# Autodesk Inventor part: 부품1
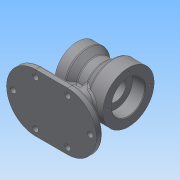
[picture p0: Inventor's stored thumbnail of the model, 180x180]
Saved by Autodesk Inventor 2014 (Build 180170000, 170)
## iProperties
Created: 2020-01
Part Number: 부품1
Material: 일반
Document SubType Name: Modeling
Designer: net
Density: 1 g/cm^3
Appearance: 기본값
Author: net
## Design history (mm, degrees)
sketch "스케치1"
  geometry: L1 (0, 0)-(80, 0); L2 (0, 26)-(20, 26); L3 (20, 26)-(20, 16); L4 (20, 16)-(63, 16); L5 (63, 16)-(63, 20); L6 (63, 20)-(80, 20); L7 (80, 20)-(80, 35); L8 (80, 35)-(64, 35); L9 (64, 35)-(53.289, 27.5); L10 (53.289, 27.5)-(38.897, 27.5); L11 (38.897, 27.5)-(24, 40); L12 (24, 40)-(0, 40); L13 (0, 40)-(0, 26)
  constraints: 26 end point, 8 parallel, 2 perpendicular, 1 horizontal, 1 vertical alignment
  dimensions: "d0" = 80 distance of L1.start L1.end; "d1" = 24 distance of L11.end L12.end; "d2" = 20 distance from line of L3 L2.start; "d3" = 17 distance of L6.end L5.end; "d4" = 80 distance between parallel lines of L7 L13; "d5" = 16 distance of L7.end L8.end; "d6" = 140 deg angle of L10 L11; "d7" = 145 deg angle of L9 L10; "d8" = 80 diameter of L12.end L1; "d9" = 55 diameter of L10 L1; "d10" = 32 diameter of L4 L1; "d11" = 40 diameter of L6 L1; "d12" = 70 diameter of L8 L1; "d13" = 52 diameter of L2 L1
revolve "회전1" sketch "스케치1" stored, may be unused: angle "d14" = 90 deg
fillet "모깎기1" dims "d15" = 0.3
chamfer "모따기1" distance "d16" = 1; stored, may be unused: second distance "d17" = 2, angle "d18" = 45 deg
chamfer "모따기2" distance "d19" = 1; stored, may be unused: second distance "d20" = 2, angle "d21" = 45 deg
node "작업 평면1"
sketch "스케치2"
  geometry: L1 (0, 40)-(24, 40) reference; L2 (0, -40)-(0, 40) reference; L3 (80, -35)-(80, 35) reference; L4 (0, -40)-(24, -40) reference; L5 (64, 35)-(80, 35) reference; L6 (64, -35)-(80, -35) reference; L7 (15, -45)-(65, -45); L8 (65, 45)-(15, 45); L9 (0, 0)-(80, 0); A1 r 45 centre (15, 0) between (15, 45) and (15, -45); A2 r 45 centre (65, 0) between (65, -45) and (65, 45); 4 further points
  constraints: 6 end point, 5 point on circle, 4 midpoint, 4 tangent, 2 centre point, 1 horizontal alignment, 1 parallel, 1 vertical alignment
  dimensions: "d24" = 45 radius of A1; "d25" = 50 distance of L7.end L7.start; "d26" = 70 distance of point (40, 0) point (-30, 0)
extrude "돌출1" join sketch "스케치2" distance "d27" = 10; taper "d28" = 0 deg
sketch "스케치3"
  geometry: L1 (-15, -45)-(-65, -45) reference; L2 (-65, 45)-(-15, 45) reference; L3 (30, 0)-(30, 53.254); L4 (-43.199, -5)-(-65, -5); L5 (-68, -2)-(-68, 2); L6 (-65, 5)-(-43.199, 5); A1 r 45 centre (-15, 0) between (-15, -45) and (-15, 45) reference; A2 r 45 centre (-15, 0) between (-15, -45) and (-15, 45) reference; A3 r 45 centre (-65, 0) between (-65, 45) and (-65, -45) reference; A4 r 16 centre (-28, 0) between (-43.199, -5) and (-43.199, 5); A5 r 3 centre (-65, -2) between (-68, -2) and (-65, -5); A6 r 3 centre (-65, 2) between (-65, 5) and (-68, 2); 1 further point
  constraints: 8 end point, 7 point on circle, 6 tangent, 3 centre point, 2 horizontal alignment, 2 perpendicular, 1 midpoint, 1 parallel
  dimensions: "d32" = 16 radius of A4; "d33" = 58 distance from line of L3 A4.centre; "d34" = 10 distance between parallel lines of L6 L4; "d35" = 3 radius of A5; "d36" = 3 radius of A6; "d37" = 50 horizontal distance of A6.centre A1.centre
extrude "돌출2" join sketch "스케치3" stored distance "d38" = 10; taper "d39" = 0 deg
sketch "스케치4"
  geometry: L1 (-42.426, -80)-(-42.426, -70) reference; L2 (-42.426, -70)-(42.426, -70) reference; L3 (42.426, -70)-(42.426, -80) reference; L4 (42.426, -80)-(-42.426, -80) reference; C1 r 40 at (0, 0) reference; C2 r 40 at (0, 0) reference; C3 r 27 at (0, 0) reference; 1 further point
  constraints: 1 vertical alignment
  dimensions: "d40" = 33 distance of C1.centre point (0, 33)
hole "구멍1" sketch "스케치4" at (0, 33) diameter "d41" = 3.242; stored, may be unused: countersink angle "d45" = 90 deg, drill point angle "d47" = 118 deg; dims "d42" = 9, "d43" = 4, "d44" = 2, "d46" = 11
sketch "스케치5"
  geometry: C1 r 35 at (0, 0) reference; 1 further point
  constraints: 1 vertical alignment
  dimensions: "d51" = 27.5 distance of C1.centre point (0, 27.5)
hole "구멍2" sketch "스케치5" at (0, 27.5) diameter "d52" = 3.242; stored, may be unused: countersink angle "d56" = 90 deg, drill point angle "d58" = 118 deg; dims "d53" = 9, "d54" = 4, "d55" = 2, "d57" = 11
sketch "스케치6"
  geometry: L1 (-15, 45)-(-65, 45) reference; L2 (-65, -45)-(-15, -45) reference; L3 (-15, 35)-(-65, 35); L4 (-65, -35)-(-15, -35); L5 (20, 0)-(-100, 0); C1 r 4.5 at (20, 0); C2 r 4.5 at (-15, -35); C3 r 4.5 at (-65, -35); C4 r 4.5 at (-100, 0); C5 r 4.5 at (-15, 35); C6 r 4.5 at (-65, 35); A1 r 35 centre (-15, 0) between (-15, -35) and (-15, 35); A2 r 35 centre (-65, 0) between (-65, 35) and (-65, -35); 4 further points
  constraints: 8 centre point, 6 end point, 6 point on circle, 5 coincident, 4 tangent, 3 horizontal alignment, 2 midpoint, 2 vertical alignment, 1 parallel
  dimensions: "d62" = 50 distance of A2.centre A1.centre; "d63" = 35 radius of A2; "d64" = 9 diameter of C1; "d65" = 9 diameter of C2; "d66" = 9 diameter of C3; "d67" = 9 diameter of C4; "d68" = 9 diameter of C5; "d69" = 9 diameter of C6; "d70" = 10 distance between parallel lines of L3 L1
extrude "돌출3" cut sketch "스케치6" stored distance "d71" = 10; taper "d72" = 0 deg
fillet "모깎기2" dims "d73" = 3
fillet "모깎기3" dims "d74" = 3
fillet "모깎기4" dims "d75" = 3
fillet "모깎기5" dims "d76" = 3
fillet "모깎기6" dims "d77" = 3
sketch "스케치7"
  geometry: L1 (0, 0)-(50, 0) reference; L2 (-45, 0)-(-45, 7) reference; 2 further points
  constraints: 1 other
  dimensions: "d78" = 4 distance from line of L1 point (25, 4); "d79" = 70 horizontal distance of point (25, 4) L2.start
feature "엠보싱1" sketch "스케치7" dims "d80" = 0.5, "d81" = 0
node "솔리드1"
pattern_circular "원형 패턴1" dims angle "d49" = 360 deg
pattern_circular "원형 패턴2" dims angle "d60" = 360 deg
node "절단 모서리 투영1"
node "절단 모서리 투영2"
